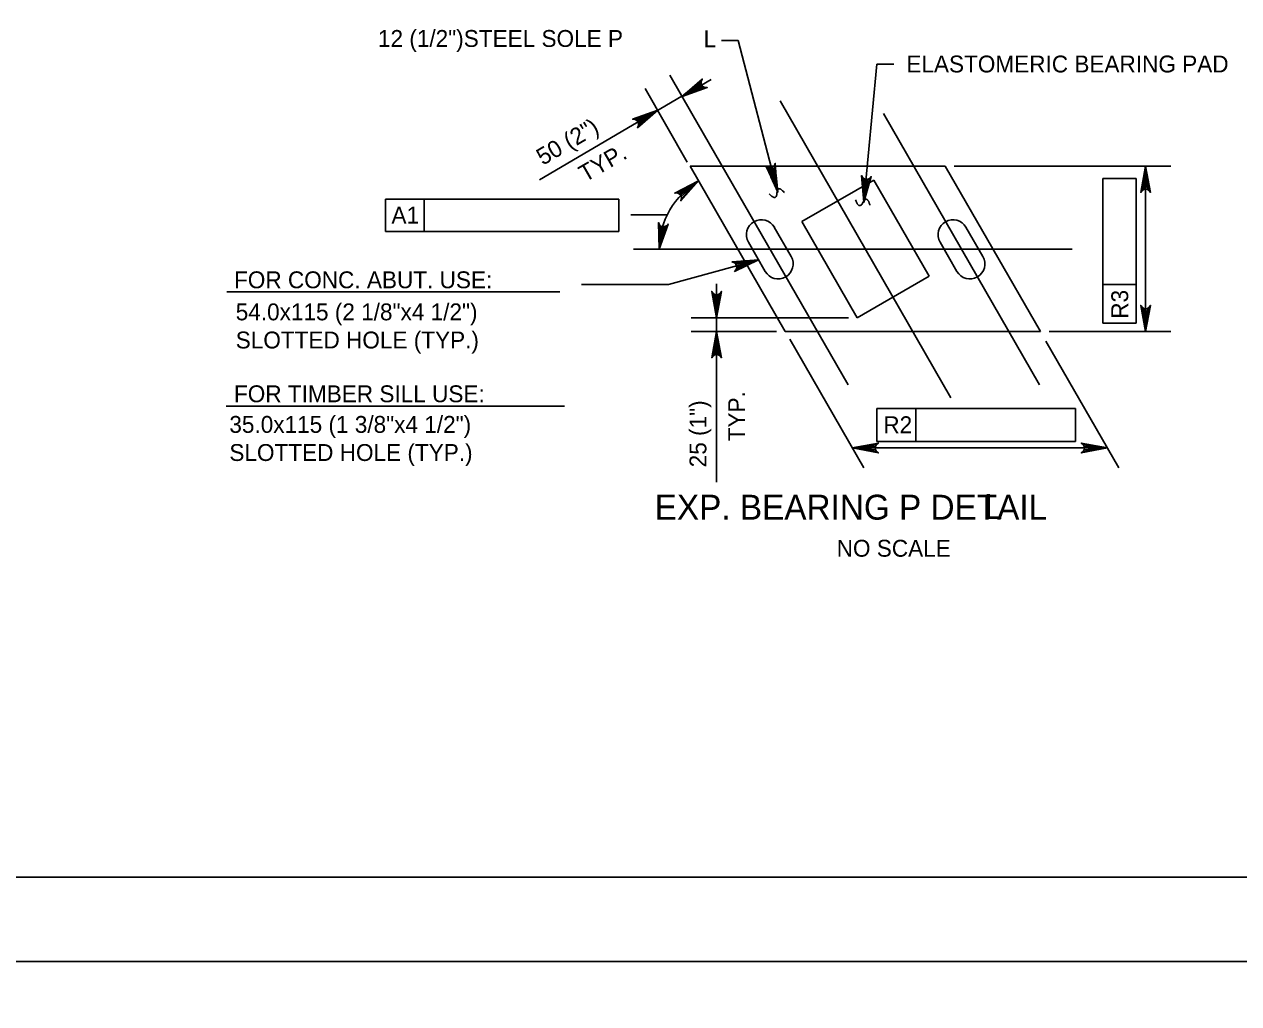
# Model space of a CAD drawing. Extents: x 638175 to 640495, y 294277 to 298435.
# Drawn here: x 638564.5 to 638780.4, y 294864 to 295038 of the extents above; entities that cross this region are included whole.
import ezdxf

# ---------------------------------------------------------------- set-up
doc = ezdxf.new("R2010")
doc.units = 0
for name, color, linetype in [('2', 7, 'Continuous'), ('3', 7, 'Continuous'), ('4', 7, 'Continuous'), ('PLT-BNDY', 7, 'Continuous')]:
    doc.layers.add(name, color=color, linetype=linetype)

# ---------------------------------------------------------------- blocks, each defined once
blk = doc.blocks.new('25S')
at = {"layer": '4'}
blk.add_open_spline([(-1.68325, 0.611625), (-0.867125, -1.69875), (0.901125, 1.69875), (1.58125, -0.611625)], degree=2, dxfattribs=at)

msp = doc.modelspace()

# ---------------------------------------------------------------- linework, layer by layer
at = {"layer": '2'}
msp.add_line((639261.46, 294886.46), (638475.46, 294886.46), dxfattribs=at)
at = {"layer": '3'}
for p, q in [((638698.83, 295024.45), (638729.23, 294971.65)), ((638683.14, 295022.17), (638710.92, 294973.94)), ((638717.22, 295022.17), (638744.99, 294973.94)), ((638682.84, 295012.82), (638728.2, 295012.82)), ((638682.84, 295012.82), (638699.77, 294983.43)), ((638728.2, 295012.82), (638745.12, 294983.43)), ((638715.49, 295010.36), (638702.7, 295002.99)), ((638715.49, 295010.36), (638725.34, 294993.26)), ((638702.7, 295002.99), (638712.55, 294985.89)), ((638697.82, 295001.98), (638700.82, 294996.78)), ((638731.89, 295001.98), (638734.89, 294996.78)), ((638696.21, 294994.13), (638693.21, 294999.33)), ((638730.28, 294994.13), (638727.29, 294999.33)), ((638712.55, 294985.89), (638725.34, 294993.26)), ((638699.77, 294983.43), (638745.12, 294983.43))]:
    msp.add_line(p, q, dxfattribs=at)
for centre, start, end in [((638695.52, 295000.66), 29.9358, 209.9358), ((638729.59, 295000.66), 29.9358, 209.9358), ((638698.51, 294995.45), 209.9358, 29.9358), ((638732.59, 294995.45), 209.9358, 29.9358)]:
    msp.add_arc(centre, 2.66, start, end, dxfattribs=at)
at = {"layer": '4'}
for p, q in [((638691.42, 295035.17), (638688.42, 295035.17)), ((638698.31, 295008.6), (638691.42, 295035.17)), ((638713.76, 295006.43), (638716.04, 295030.99)), ((638716.04, 295030.99), (638719.04, 295030.99)), ((638683.14, 295022.17), (638679.26, 295029)), ((638682.33, 295013.54), (638674.88, 295026.66)), ((638681.41, 295025.22), (638686.59, 295028.21)), ((638681.37, 295025.29), (638656.07, 295010.4)), ((638729.77, 295012.82), (638768.33, 295012.82)), ((638763.83, 294983.43), (638763.83, 295012.82)), ((638756.25, 294984.91), (638756.25, 295010.66)), ((638756.25, 295010.66), (638762.16, 295010.66)), ((638762.16, 295010.66), (638762.16, 294984.91)), ((638628.68, 295006.96), (638670.2, 295006.96)), ((638628.68, 295001.19), (638628.68, 295006.96)), ((638635.57, 295001.19), (638635.57, 295006.96)), ((638670.2, 295006.96), (638670.2, 295001.19)), ((638678.78, 295004.2), (638672.29, 295004.2)), ((638670.2, 295001.19), (638628.68, 295001.19)), ((638672.76, 294998.05), (638750.77, 294998.05)), ((638695.02, 294996.19), (638679, 294991.82)), ((638679, 294991.82), (638663.51, 294991.82)), ((638687.55, 294985.89), (638687.55, 294991.89)), ((638600.49, 294990.5), (638659.69, 294990.5)), ((638762.16, 294991.8), (638756.25, 294991.8)), ((638710.98, 294985.89), (638683.05, 294985.89)), ((638687.55, 294985.89), (638687.55, 294956.69)), ((638698.2, 294983.43), (638683.05, 294983.43)), ((638746.69, 294983.43), (638768.33, 294983.43)), ((638762.16, 294984.91), (638756.25, 294984.91)), ((638713.71, 294959.23), (638700.56, 294982.06)), ((638759.06, 294959.23), (638746.11, 294981.73)), ((638600.38, 294970.17), (638660.53, 294970.17)), ((638716.07, 294969.78), (638751.37, 294969.78)), ((638716.07, 294963.87), (638716.07, 294969.78)), ((638722.96, 294963.87), (638722.96, 294969.78)), ((638751.37, 294969.78), (638751.37, 294963.87)), ((638751.37, 294963.87), (638716.07, 294963.87)), ((638711.68, 294962.74), (638757.04, 294962.74))]:
    msp.add_line(p, q, dxfattribs=at)
for points in [[(638683.74, 295027.14), (638684.24, 295026.28), (638681.39, 295025.21)], [(638674.27, 295021.69), (638674.77, 295020.83), (638677.12, 295022.76)], [(638763.33, 295009.82), (638764.33, 295009.82), (638763.83, 295012.82)], [(638698.15, 295011.22), (638697.18, 295010.96), (638698.42, 295008.19)], [(638714.54, 295009.4), (638713.54, 295009.49), (638713.76, 295006.46)], [(638691.74, 294995.81), (638692.01, 294994.85), (638694.77, 294996.12)], [(638687.05, 294988.89), (638688.05, 294988.89), (638687.55, 294985.89)], [(638763.33, 294986.43), (638764.33, 294986.43), (638763.83, 294983.43)], [(638687.05, 294980.43), (638688.05, 294980.43), (638687.55, 294983.43)], [(638714.68, 294963.24), (638714.68, 294962.24), (638711.68, 294962.74)], [(638754.04, 294963.24), (638754.04, 294962.24), (638757.04, 294962.74)]]:
    msp.add_lwpolyline(points, close=True, dxfattribs=at)
for points in [[(638681.41, 295025.22), (638685.01, 295028.31), (638684.82, 295027.91), (638684.82, 295027.55), (638684.93, 295027.25), (638685.13, 295027.01), (638685.44, 295026.83), (638685.88, 295026.79), (638681.41, 295025.22), (638685.44, 295026.83), (638685.13, 295027.01), (638681.41, 295025.22), (638684.93, 295027.25), (638684.82, 295027.55), (638681.41, 295025.22), (638684.82, 295027.91)], [(638677.09, 295022.77), (638673.51, 295019.65), (638673.7, 295020.05), (638673.7, 295020.41), (638673.58, 295020.71), (638673.38, 295020.95), (638673.06, 295021.13), (638672.63, 295021.16), (638677.09, 295022.77), (638673.06, 295021.13), (638673.38, 295020.95), (638677.09, 295022.77), (638673.58, 295020.71), (638673.7, 295020.41), (638677.09, 295022.77), (638673.7, 295020.05)], [(638698.31, 295008.6), (638696.3, 295012.89), (638696.63, 295012.61), (638696.98, 295012.51), (638697.29, 295012.53), (638697.58, 295012.66), (638697.84, 295012.92), (638697.99, 295013.33), (638698.31, 295008.6), (638697.84, 295012.92), (638697.58, 295012.66), (638698.31, 295008.6), (638697.29, 295012.53), (638696.98, 295012.51), (638698.31, 295008.6), (638696.63, 295012.61)], [(638763.83, 295012.82), (638764.7, 295008.16), (638764.45, 295008.52), (638764.14, 295008.7), (638763.83, 295008.76), (638763.52, 295008.7), (638763.2, 295008.52), (638762.96, 295008.16), (638763.83, 295012.82), (638763.2, 295008.52), (638763.52, 295008.7), (638763.83, 295012.82), (638763.83, 295008.76), (638764.14, 295008.7), (638763.83, 295012.82), (638764.45, 295008.52)], [(638684.35, 295010.2), (638681.18, 295006.67), (638681.32, 295007.09), (638681.27, 295007.45), (638681.13, 295007.73), (638680.89, 295007.94), (638680.56, 295008.08), (638680.12, 295008.06), (638684.35, 295010.2), (638680.56, 295008.08), (638680.89, 295007.94), (638684.35, 295010.2), (638681.13, 295007.73), (638681.27, 295007.45), (638684.35, 295010.2), (638681.32, 295007.09)], [(638713.76, 295006.43), (638713.32, 295011.15), (638713.53, 295010.77), (638713.83, 295010.56), (638714.13, 295010.47), (638714.45, 295010.5), (638714.78, 295010.65), (638715.06, 295010.99), (638713.76, 295006.43), (638714.78, 295010.65), (638714.45, 295010.5), (638713.76, 295006.43), (638714.13, 295010.47), (638713.83, 295010.56), (638713.76, 295006.43), (638713.53, 295010.77)], [(638677.35, 294998.06), (638677.2, 295002.8), (638677.39, 295002.4), (638677.67, 295002.17), (638677.97, 295002.07), (638678.29, 295002.08), (638678.63, 295002.21), (638678.92, 295002.53), (638677.35, 294998.06), (638678.63, 295002.21), (638678.29, 295002.08), (638677.35, 294998.06), (638677.97, 295002.07), (638677.67, 295002.17), (638677.35, 294998.06), (638677.39, 295002.4)], [(638695.02, 294996.19), (638690.76, 294994.12), (638691.04, 294994.45), (638691.13, 294994.8), (638691.11, 294995.12), (638690.97, 294995.41), (638690.71, 294995.66), (638690.3, 294995.8), (638695.02, 294996.19), (638690.71, 294995.66), (638690.97, 294995.41), (638695.02, 294996.19), (638691.11, 294995.12), (638691.13, 294994.8), (638695.02, 294996.19), (638691.04, 294994.45)], [(638687.55, 294985.89), (638686.68, 294990.56), (638686.92, 294990.2), (638687.24, 294990.01), (638687.55, 294989.96), (638687.86, 294990.01), (638688.17, 294990.2), (638688.42, 294990.56), (638687.55, 294985.89), (638688.17, 294990.2), (638687.86, 294990.01), (638687.55, 294985.89), (638687.55, 294989.96), (638687.24, 294990.01), (638687.55, 294985.89), (638686.92, 294990.2)], [(638763.83, 294983.43), (638762.96, 294988.09), (638763.2, 294987.74), (638763.52, 294987.55), (638763.83, 294987.5), (638764.14, 294987.55), (638764.45, 294987.74), (638764.7, 294988.09), (638763.83, 294983.43), (638764.45, 294987.74), (638764.14, 294987.55), (638763.83, 294983.43), (638763.83, 294987.5), (638763.52, 294987.55), (638763.83, 294983.43), (638763.2, 294987.74)], [(638687.55, 294983.43), (638688.42, 294978.77), (638688.17, 294979.13), (638687.86, 294979.32), (638687.55, 294979.37), (638687.24, 294979.32), (638686.92, 294979.13), (638686.68, 294978.77), (638687.55, 294983.43), (638686.92, 294979.13), (638687.24, 294979.32), (638687.55, 294983.43), (638687.55, 294979.37), (638687.86, 294979.32), (638687.55, 294983.43), (638688.17, 294979.13)], [(638711.68, 294962.74), (638716.34, 294963.61), (638715.99, 294963.36), (638715.8, 294963.05), (638715.75, 294962.74), (638715.8, 294962.43), (638715.99, 294962.11), (638716.34, 294961.87), (638711.68, 294962.74), (638715.99, 294962.11), (638715.8, 294962.43), (638711.68, 294962.74), (638715.75, 294962.74), (638715.8, 294963.05), (638711.68, 294962.74), (638715.99, 294963.36)], [(638757.04, 294962.74), (638752.38, 294961.87), (638752.74, 294962.11), (638752.93, 294962.43), (638752.98, 294962.74), (638752.93, 294963.05), (638752.74, 294963.36), (638752.38, 294963.61), (638757.04, 294962.74), (638752.74, 294963.36), (638752.93, 294963.05), (638757.04, 294962.74), (638752.98, 294962.74), (638752.93, 294962.43), (638757.04, 294962.74), (638752.74, 294962.11)]]:
    msp.add_lwpolyline(points, dxfattribs=at)
msp.add_arc((638691.35, 294998.05), 14, 119.9358, 179.9966, dxfattribs=at)
msp.add_open_spline([(638712.25, 295006.87), (638712.89, 295005.05), (638714.29, 295007.73), (638714.82, 295005.91)], degree=2, dxfattribs=at)
at = {"layer": 'PLT-BNDY'}
for points in [[(638435.46, 295465.46), (639276.46, 295465.46), (639276.46, 294871.46), (638435.46, 294871.46)], [(638435.46, 294871.46), (639276.46, 294871.46), (639276.46, 294277.46), (638435.46, 294277.46)]]:
    msp.add_lwpolyline(points, close=True, dxfattribs=at)

# ---------------------------------------------------------------- block references
at = {"layer": '4', "xscale": 0.7874015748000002, "yscale": 0.7874015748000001, "rotation": 24.604977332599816}
msp.add_blockref('25S', (638698.28, 295008.04), dxfattribs=at)

# ---------------------------------------------------------------- texts
at = {"layer": '4'}
for s, height, p in [('12 (1/2")STEEL SOLE P', 3, (638627.35, 295034.03)), ('L', 3, (638685.25, 295033.97)), ('ELASTOMERIC BEARING PAD', 3, (638721.29, 295029.49)), ('A1', 3, (638629.75, 295002.62)), ('FOR CONC. ABUT. USE:', 3, (638601.76, 294991.13)), ('54.0x115 (2 1/8"x4 1/2")', 3, (638602.06, 294985.43)), ('SLOTTED HOLE (TYP.)', 3, (638602.06, 294980.43)), ('FOR TIMBER SILL USE:', 3, (638601.75, 294970.87)), ('35.0x115 (1 3/8"x4 1/2")', 3, (638600.93, 294965.43)), ('R2', 3, (638717.2, 294965.37)), ('SLOTTED HOLE (TYP.)', 3, (638600.93, 294960.43)), ('EXP. BEARING P DETAIL', 4.4292, (638676.55, 294950)), ('L', 4.43, (638735.1, 294950.12)), ('NO SCALE', 3, (638708.9, 294943.41))]:
    msp.add_text(s, height=height, dxfattribs=at).set_placement(p)
for s, rotation, p in [('50 (2")', 30.4659, (638656.66, 295012.89)), ('TYP.', 29.9358, (638664.18, 295009.91)), ('R3', 90, (638760.73, 294985.71)), ('TYP.', 90, (638692.62, 294963.92)), ('25 (1")', 90, (638685.74, 294959.3))]:
    msp.add_text(s, height=3, rotation=rotation, dxfattribs=at).set_placement(p)

doc.saveas('drawing.dxf')
